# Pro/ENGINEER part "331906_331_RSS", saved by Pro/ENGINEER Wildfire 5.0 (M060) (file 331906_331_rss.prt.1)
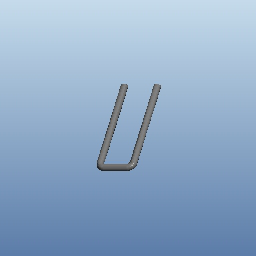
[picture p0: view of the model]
Units: PSOLunit; MM, KILOGRAM, SECS

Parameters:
  NN = "331906"
  NT = "Stainless Steel - Latch Clamps - 331-RSS Series - Hook"
  NB = "331906-331-rss"
  NBSYN = "$PN.-$S."
  LINA = "331906-331-rss"
  S1 = "331-SS"
  S = "331-rss"
  PN = "331906"
  ARTICLENO = "331906-331-rss"
  BOMINFO = "331906-331-rss"
  CREATOR = "CADENAS GmbH"
  PLACEMENT = "A"
  METRIC = "NO"

Other parameters: A, B, L, NDM, KDM, R, NUTSIZE, C, THREADS_PER_INCH, SURF_AREA, MASS

Other named items: COORD, DEF-PLANE-AXIS, DEF-PLANE-AXIS-INV, CS0, CS1, CS3, CS5, HOOK_TO_CLEAT_CSYS, HOOK_TO_PIN_CSYS, CONN, MASS, RIGHT, TOP, FRONT, HOOK_TO_CLEAT_XPLN, HOOK_TO_CLEAT_YPLN, HOOK_TO_CLEAT_ZPLN, HOOK_TO_PIN_XPLN, HOOK_TO_PIN_YPLN, HOOK_TO_PIN_ZPLN, HOOK_TO_CLEAT_ZAXS, HOOK_TO_PIN_ZAXS

Named dimensions: THLEN, THDIA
